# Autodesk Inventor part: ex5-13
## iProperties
Shininess: 64.0
Length Units: 11272
Angle Units: 11279
Time Units: 11290
Mass Units: 11286
Length Display Precision: 3
Angle Display Precision: 2
Compacted: True
Part Number: ex5-13
Document SubType Name: Modeling
Created: 2003-11
Designer: Elise Moss
Cost Center: 0.1 lbmass
Authority: 1.91 in^3
Manufacturer: Standard
Standards Organization: Custom
Density: 0.0
Volumn: 0.0
Area: 0.0
PropertySet Name: Model Information
Control State: 0
Master: False
Checked Out: False
SaveDate: 2003-11-14
SaveTime: 19:49
TotalMass: 0.1 lbmass
TotalVolume: 1.91 in^3
Author: Elise Moss
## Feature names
1. Loft1
2. Shell1
3. Extrusion1
4. Sweep1
5. Extrusion2
6. Coil1
7. Fillet1
8. Fillet2
9. FaceDraft1
